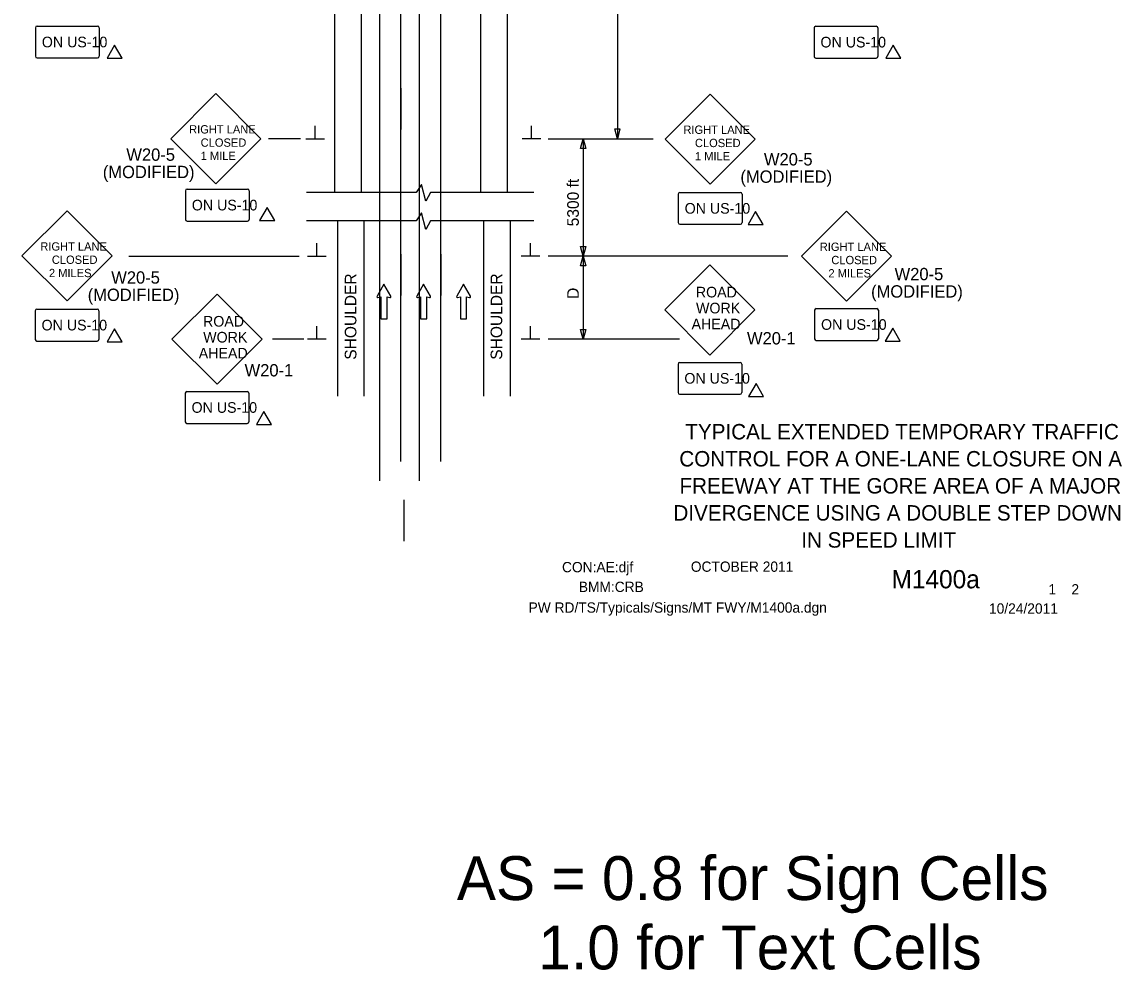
# Model space of a CAD drawing. Extents: x 16751 to 18479, y 5718 to 6974.
# Drawn here: x 16765 to 17428, y 5718 to 6290 of the extents above; entities that cross this region are included whole.
import ezdxf

# ---------------------------------------------------------------- set-up
doc = ezdxf.new("R2010")
doc.units = 0
for name, color, linetype in [('ALI_LEGAL_EX', 7, 'Continuous'), ('BORDER', 7, 'Continuous'), ('BORDER_SIGNAL_WO', 7, 'Continuous'), ('MT_SCRATCH_LEVEL_E', 7, 'Continuous'), ('PAVT_EDGE_EX', 7, 'Continuous'), ('TRAFFIC_SIGNS_PR', 7, 'Continuous'), ('TYPICAL_TEXT_DIMEN_PR', 7, 'Continuous')]:
    doc.layers.add(name, color=color, linetype=linetype)

msp = doc.modelspace()

# ---------------------------------------------------------------- linework, layer by layer
at = {"layer": 'ALI_LEGAL_EX'}
for p, q in [((16980.68, 6974.12), (16980.68, 6155.98)), ((17004.68, 6974.12), (17004.68, 6155.98)), ((16980.68, 6877.04), (16980.68, 6013.12)), ((17004.68, 6877.04), (17004.68, 6013.12)), ((16993.65, 6024.8), (16993.65, 6525.15)), ((17017.65, 6024.8), (17017.65, 6525.15))]:
    msp.add_line(p, q, dxfattribs=at)
for points in [[(16993.75, 6224.79), (16993.75, 6249.79)], [(17017.75, 6224.79), (17017.75, 6249.79)], [(16993.8, 6124.79), (16993.8, 6149.79)], [(17017.8, 6124.79), (17017.8, 6149.79)], [(16995.37, 6001.71), (16995.37, 5976.71)]]:
    msp.add_lwpolyline(points, dxfattribs=at)
at = {"layer": 'MT_SCRATCH_LEVEL_E'}
for p, q in [((16983.38, 6131.58), (16979.27, 6124.34)), ((16987.53, 6124.34), (16983.38, 6131.58)), ((17007.29, 6131.58), (17003.18, 6124.34)), ((17011.44, 6124.34), (17007.29, 6131.58)), ((17031.34, 6131.58), (17027.23, 6124.34)), ((17035.49, 6124.34), (17031.34, 6131.58)), ((16979.76, 6123.66), (16981.53, 6123.97)), ((16981.53, 6123.97), (16981.53, 6110.72)), ((16985.27, 6110.72), (16985.27, 6123.97)), ((16985.27, 6123.97), (16987.05, 6123.66)), ((17003.66, 6123.66), (17005.44, 6123.97)), ((17005.44, 6123.97), (17005.44, 6110.72)), ((17009.18, 6110.72), (17009.18, 6123.97)), ((17009.18, 6123.97), (17010.96, 6123.66)), ((17027.71, 6123.66), (17029.49, 6123.97)), ((17029.49, 6123.97), (17029.49, 6110.72)), ((17033.23, 6110.72), (17033.23, 6123.97)), ((17033.23, 6123.97), (17035.01, 6123.66)), ((16981.53, 6110.72), (16985.27, 6110.72)), ((17005.44, 6110.72), (17009.18, 6110.72)), ((17029.49, 6110.72), (17033.23, 6110.72))]:
    msp.add_line(p, q, dxfattribs=at)
for centre, start, end in [((16979.68, 6124.12), 150.42484, 279.96381), ((16987.12, 6124.12), 260.03619, 29.77312), ((17003.58, 6124.12), 150.42484, 279.96381), ((17011.03, 6124.12), 260.03619, 29.77312), ((17027.64, 6124.12), 150.42484, 279.96381), ((17035.08, 6124.12), 260.03619, 29.77312)]:
    msp.add_arc(centre, 0.463, start, end, dxfattribs=at)
at = {"layer": 'PAVT_EDGE_EX'}
for p, q in [((16953.65, 6525.15), (16953.65, 6186.91)), ((16969.65, 6525.15), (16969.65, 6186.91)), ((17041.65, 6525.15), (17041.65, 6186.91)), ((17057.65, 6525.15), (17057.65, 6186.91)), ((16955.37, 6169.77), (16955.37, 6064.1)), ((16971.37, 6169.77), (16971.37, 6064.1)), ((17043.37, 6169.77), (17043.37, 6064.1)), ((17059.37, 6169.77), (17059.37, 6064.1))]:
    msp.add_line(p, q, dxfattribs=at)
at = {"layer": 'TRAFFIC_SIGNS_PR'}
for p, q in [((16773.46, 6286.18), (16773.46, 6268.98)), ((16774.46, 6287.18), (16810.87, 6287.18)), ((16811.87, 6286.18), (16811.87, 6268.98)), ((17242.56, 6286.09), (17242.56, 6268.89)), ((17243.56, 6287.09), (17279.96, 6287.09)), ((17280.96, 6286.09), (17280.96, 6268.89)), ((16774.46, 6267.98), (16810.87, 6267.98)), ((17243.56, 6267.89), (17279.96, 6267.89)), ((16882.15, 6246.46), (16855, 6219.31)), ((16909.3, 6219.31), (16882.15, 6246.46)), ((17179.93, 6246.23), (17152.78, 6219.08)), ((17207.08, 6219.08), (17179.93, 6246.23)), ((16855, 6219.31), (16882.15, 6192.16)), ((16882.15, 6192.16), (16909.3, 6219.31)), ((17152.78, 6219.08), (17179.93, 6191.93)), ((17179.93, 6191.93), (17207.08, 6219.08)), ((16863.82, 6187.9), (16863.82, 6170.7)), ((16864.82, 6188.9), (16901.23, 6188.9)), ((16902.23, 6187.9), (16902.23, 6170.7)), ((17160.73, 6185.93), (17160.73, 6168.73)), ((17161.73, 6186.93), (17198.14, 6186.93)), ((17199.14, 6185.93), (17199.14, 6168.73)), ((16792.51, 6175.89), (16765.35, 6148.74)), ((16819.66, 6148.74), (16792.51, 6175.89)), ((16864.82, 6169.7), (16901.23, 6169.7)), ((17262.09, 6175.7), (17234.94, 6148.55)), ((17289.24, 6148.55), (17262.09, 6175.7)), ((17161.73, 6167.73), (17198.14, 6167.73)), ((16765.35, 6148.74), (16792.51, 6121.59)), ((16792.51, 6121.59), (16819.66, 6148.74)), ((17179.77, 6143.28), (17152.61, 6116.12)), ((17206.92, 6116.12), (17179.77, 6143.28)), ((17234.94, 6148.55), (17262.09, 6121.4)), ((17262.09, 6121.4), (17289.24, 6148.55)), ((16882.87, 6125.71), (16855.71, 6098.55)), ((16910.02, 6098.55), (16882.87, 6125.71)), ((17243.89, 6116.95), (17280.3, 6116.95)), ((16773.3, 6115.59), (16773.3, 6098.39)), ((16774.3, 6116.59), (16810.71, 6116.59)), ((16811.71, 6115.59), (16811.71, 6098.39)), ((17152.61, 6116.12), (17179.77, 6088.96)), ((17179.77, 6088.96), (17206.92, 6116.12)), ((17242.89, 6115.95), (17242.89, 6098.75)), ((17281.3, 6115.95), (17281.3, 6098.75)), ((16774.3, 6097.39), (16810.71, 6097.39)), ((16855.71, 6098.55), (16882.87, 6071.4)), ((16882.87, 6071.4), (16910.02, 6098.55)), ((17243.89, 6097.75), (17280.3, 6097.75)), ((17160.56, 6083.52), (17160.56, 6066.32)), ((17161.56, 6084.52), (17197.97, 6084.52)), ((17198.97, 6083.52), (17198.97, 6066.32)), ((16863.67, 6065.95), (16863.67, 6048.75)), ((16864.67, 6066.95), (16901.07, 6066.95)), ((16902.07, 6065.95), (16902.07, 6048.75)), ((17161.56, 6065.32), (17197.97, 6065.32)), ((16864.67, 6047.75), (16901.07, 6047.75))]:
    msp.add_line(p, q, dxfattribs=at)
for centre, start, end in [((16774.46, 6286.18), 90, 180), ((16810.87, 6286.18), 0, 90), ((17243.56, 6286.09), 90, 180), ((17279.96, 6286.09), 0, 90), ((16774.46, 6268.98), 180, 270), ((16810.87, 6268.98), 270, 0), ((17243.56, 6268.89), 180, 270), ((17279.96, 6268.89), 270, 0), ((16864.82, 6187.9), 90, 180), ((16901.23, 6187.9), 0, 90), ((17161.73, 6185.93), 90, 180), ((17198.14, 6185.93), 0, 90), ((16864.82, 6170.7), 180, 270), ((16901.23, 6170.7), 270, 0), ((17161.73, 6168.73), 180, 270), ((17198.14, 6168.73), 270, 0), ((17243.89, 6115.95), 90, 180), ((17280.3, 6115.95), 0, 90), ((16774.3, 6115.59), 90, 180), ((16810.71, 6115.59), 0, 90), ((16774.3, 6098.39), 180, 270), ((16810.71, 6098.39), 270, 0), ((17243.89, 6098.75), 180, 270), ((17280.3, 6098.75), 270, 0), ((17161.56, 6083.52), 90, 180), ((17197.97, 6083.52), 0, 90), ((16864.67, 6065.95), 90, 180), ((16901.07, 6065.95), 0, 90), ((17161.56, 6066.32), 180, 270), ((17197.97, 6066.32), 270, 0), ((16864.67, 6048.75), 180, 270), ((16901.07, 6048.75), 270, 0)]:
    msp.add_arc(centre, 1, start, end, dxfattribs=at)
at = {"layer": 'TYPICAL_TEXT_DIMEN_PR'}
for p, q in [((17124.01, 6619.33), (17124.01, 6219.33)), ((16941.96, 6219.33), (16941.96, 6227.11)), ((17072.21, 6219.33), (17072.21, 6227.11)), ((17124.01, 6219.33), (17122.44, 6225.19)), ((17122.44, 6225.19), (17124.01, 6225.19)), ((17124.01, 6225.19), (17125.58, 6225.19)), ((17125.58, 6225.19), (17124.01, 6219.33)), ((16933.16, 6219.33), (16913.94, 6219.33)), ((16936.33, 6219.33), (16947.58, 6219.33)), ((17077.83, 6219.33), (17066.58, 6219.33)), ((17082.37, 6219.33), (17145.63, 6219.33)), ((17101.8, 6213.47), (17103.37, 6219.33)), ((17103.37, 6219.33), (17103.37, 6148.55)), ((17103.37, 6219.33), (17104.94, 6213.47)), ((17103.37, 6213.47), (17101.8, 6213.47)), ((17104.94, 6213.47), (17103.37, 6213.47)), ((17005.97, 6191.71), (17002.72, 6186.91)), ((17008.71, 6181.77), (17005.97, 6191.71)), ((17002.72, 6186.91), (16936.78, 6186.91)), ((17011.46, 6186.91), (17008.71, 6181.77)), ((17073.79, 6186.91), (17011.46, 6186.91)), ((17002.72, 6169.77), (16936.78, 6169.77)), ((17005.97, 6174.57), (17002.72, 6169.77)), ((17008.71, 6164.63), (17005.97, 6174.57)), ((17011.46, 6169.77), (17008.71, 6164.63)), ((17073.79, 6169.77), (17011.46, 6169.77)), ((16942.99, 6148.55), (16942.99, 6156.34)), ((17071.74, 6148.55), (17071.74, 6156.34)), ((17103.37, 6148.55), (17101.8, 6154.41)), ((17101.8, 6154.41), (17103.37, 6154.41)), ((17103.37, 6154.41), (17104.94, 6154.41)), ((17104.94, 6154.41), (17103.37, 6148.55)), ((16829.7, 6148.55), (16932.37, 6148.55)), ((16937.37, 6148.55), (16948.62, 6148.55)), ((17077.37, 6148.55), (17066.12, 6148.55)), ((17226.77, 6148.55), (17082.37, 6148.55)), ((17101.8, 6142.69), (17103.37, 6148.55)), ((17103.37, 6148.55), (17103.37, 6098.55)), ((17103.37, 6148.55), (17104.94, 6142.69)), ((17103.37, 6142.69), (17101.8, 6142.69)), ((17104.94, 6142.69), (17103.37, 6142.69)), ((16942.99, 6098.55), (16942.99, 6106.34)), ((17071.74, 6098.55), (17071.74, 6106.34)), ((17103.37, 6098.55), (17101.8, 6104.41)), ((17101.8, 6104.41), (17103.37, 6104.41)), ((17103.37, 6104.41), (17104.94, 6104.41)), ((17104.94, 6104.41), (17103.37, 6098.55)), ((16935.19, 6098.55), (16916.34, 6098.55)), ((16948.62, 6098.55), (16937.37, 6098.55)), ((17077.37, 6098.55), (17066.12, 6098.55)), ((17161.56, 6098.55), (17082.37, 6098.55))]:
    msp.add_line(p, q, dxfattribs=at)
for points in [[(16821.17, 6275.75), (16816.65, 6267.92), (16825.7, 6267.92)], [(17290.26, 6275.66), (17285.74, 6267.83), (17294.79, 6267.83)], [(16913.05, 6177.8), (16908.53, 6169.97), (16917.58, 6169.97)], [(17207.28, 6175.37), (17202.76, 6167.54), (17211.81, 6167.54)], [(16821.11, 6104.73), (16816.58, 6096.89), (16825.64, 6096.89)], [(17289.89, 6105.21), (17285.37, 6097.38), (17294.42, 6097.38)], [(17207.56, 6071.82), (17203.04, 6063.98), (17212.09, 6063.98)], [(16911.12, 6054.95), (16906.6, 6047.12), (16915.65, 6047.12)]]:
    msp.add_lwpolyline(points, close=True, dxfattribs=at)

# ---------------------------------------------------------------- texts
at = {"layer": 'BORDER'}
for s, p in [('TYPICAL EXTENDED TEMPORARY TRAFFIC', (17164.97, 6038.11)), ('CONTROL FOR A ONE-LANE CLOSURE ON A', (17161.34, 6021.81)), ('FREEWAY AT THE GORE AREA OF A MAJOR', (17161.47, 6005.51)), (' DIVERGENCE USING A DOUBLE STEP DOWN ', (17154.34, 5989.2)), ('IN SPEED LIMIT', (17234.84, 5972.9))]:
    msp.add_text(s, height=9.3, dxfattribs=at).set_placement(p)
at = {"layer": 'BORDER_SIGNAL_WO'}
for s, height, p in [('CON:AE:djf  ', 6.2, (17090.69, 5958.06)), ('    OCTOBER 2011    ', 6.2, (17159.08, 5958.34)), ('    M1400a   ', 11, (17272.86, 5948.38)), ('BMM:CRB   ', 6.2, (17100.81, 5946.17)), (' 1    2 ', 6.2, (17381.45, 5944.7)), ('PW RD/TS/Typicals/Signs/MT FWY/M1400a.dgn      ', 6.2, (17070.55, 5933.71)), ('10/24/2011    ', 6.2, (17347.93, 5933.13)), ('AS = 0.8 for Sign Cells', 26.4241, (17027.34, 5760.56)), ('     1.0 for Text Cells', 26.4241, (17027.34, 5718.77))]:
    msp.add_text(s, height=height, dxfattribs=at).set_placement(p)
at = {"layer": 'TRAFFIC_SIGNS_PR'}
for s, height, p in [('ON US-10', 6.401, (16777.3, 6274.38)), ('ON US-10', 6.401, (17246.39, 6274.29)), ('RIGHT LANE', 4.999, (16866.04, 6222.46)), ('RIGHT LANE', 4.999, (17163.82, 6222.24)), ('CLOSED', 4.999, (16872.99, 6214.46)), ('CLOSED', 4.999, (17170.77, 6214.24)), ('W20-5', 7.439, (16828.22, 6205.99)), ('1 MILE', 4.999, (16872.99, 6206.46)), ('1 MILE', 4.999, (17170.77, 6206.24)), ('W20-5', 7.439, (17212.33, 6203.17)), ('(MODIFIED)', 7.439, (16814.04, 6195.55)), ('(MODIFIED)', 7.439, (17198.15, 6192.73)), ('ON US-10', 6.401, (16867.66, 6176.1)), ('ON US-10', 6.401, (17164.57, 6174.14)), ('RIGHT LANE', 4.999, (16776.39, 6151.89)), ('RIGHT LANE', 4.999, (17245.97, 6151.7)), ('CLOSED', 4.999, (16783.34, 6143.89)), ('CLOSED', 4.999, (17252.93, 6143.7)), ('2 MILES', 4.999, (16781.59, 6135.89)), ('W20-5', 7.439, (16819.12, 6131.97)), ('2 MILES', 4.999, (17251.18, 6135.71)), ('W20-5', 7.439, (17291.06, 6134.01)), ('ROAD', 6.401, (17171.31, 6123.66)), ('(MODIFIED)', 7.439, (17276.88, 6123.57)), ('(MODIFIED)', 7.439, (16804.94, 6121.53)), ('WORK', 6.401, (17171.42, 6114.05)), ('ON US-10', 6.401, (16777.14, 6103.79)), ('ROAD', 6.401, (16874.41, 6106.09)), ('AHEAD', 6.401, (17168.73, 6104.45)), ('ON US-10', 6.401, (17246.73, 6104.15)), ('WORK', 6.401, (16874.52, 6096.49)), ('W20-1', 7.441, (17202.11, 6095.35)), ('AHEAD', 6.401, (16871.83, 6086.89)), ('W20-1', 7.441, (16899.46, 6076.07)), ('ON US-10', 6.401, (17164.4, 6071.72)), ('ON US-10', 6.401, (16867.5, 6054.15))]:
    msp.add_text(s, height=height, dxfattribs=at).set_placement(p)
at = {"layer": 'TYPICAL_TEXT_DIMEN_PR'}
for s, p in [('5300 ft', (17100.81, 6166.51)), ('SHOULDER', (16966.81, 6086.13)), ('SHOULDER', (17054.67, 6086.13)), ('D', (17100.81, 6122.77))]:
    msp.add_text(s, height=7, rotation=90, dxfattribs=at).set_placement(p)

doc.saveas('drawing.dxf')
